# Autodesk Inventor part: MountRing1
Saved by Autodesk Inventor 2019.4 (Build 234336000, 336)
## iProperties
Created: 2020-04
Part Number: MountRing1
Material: Generic
Document SubType Name: Modeling
Designer: Administrator
Density: 1 g/cm^3
Appearance: Default
Title: MountRing1
Author: Administrator
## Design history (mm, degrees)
feature "MountRing1"
body "Solid1"
